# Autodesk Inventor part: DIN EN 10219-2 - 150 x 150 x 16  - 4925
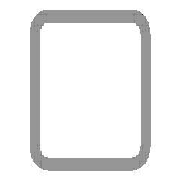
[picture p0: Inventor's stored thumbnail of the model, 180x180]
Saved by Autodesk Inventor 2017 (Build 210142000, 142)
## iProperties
IsCustomPart: 1
Created: 2017-11
Part Number: DIN EN 10219-2 - 150 x 150 x 16  - 4925
Material: Steel, Mild
Description: Cold formed welded structural hollow sections of non-alloy and fine grain structural steel
Document SubType Name: Modeling
Standard: DIN
Designer: iusti
Standard Revision: 2006-07
Standards Organization: DIN
Language: en-US
Size Designation: 150 x 150 x 16
Categories: <MemberInstance><Categories><Category DisplayName="Structural Shapes" InternalName="089c4875-fa83-4c05-b084-43b9cc11f5ed" Mnemonic="GRDR"><CategoryParameter Dis
Stock Number: 150 x 150 x 16
Density: 7.85 g/cm^3
Appearance: Semi-Polished
Mass: 289079 g
Surface Area: 46181.3 cm^2
Volume: 36825.4 cm^3
_CCFamilyMember: 76
_CCFamilyDisplayName: DIN EN 10219-2 (Square Hollow Section - Cold Formed) - Cold formed welded structural hollow sections of non-alloy and fine grain structural steel
_FrameMemberDoc: Frame Member File
_Version: 15.0.0
_GetPNFromCC: 1
G_L: 4925.000 mm
G_W: 150.000 mm
G_H: 150.000 mm
+38AB50A9-5FEF-434A-B58F-2C43C3F5CDA6+CUTDETAIL1: Cut
Author: iusti
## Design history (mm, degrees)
node "Start plane"
node "End plane"
sketch "Sketch"
  geometry: L1 (-75, -27)-(-75, 27); L2 (-27, 75)-(27, 75); L3 (75, 27)-(75, -27); L4 (27, -75)-(-27, -75); L5 (-27, 59)-(27, 59); L6 (59, 27)-(59, -27); L7 (27, -59)-(-27, -59); L8 (-59, -27)-(-59, 27); L9 (0, 153.918)-(0, -153.918) reference; L10 (-153.918, 0)-(153.918, 0) reference; A1 r 48 centre (-27, -27) between (-75, -27) and (-27, -75); A2 r 48 centre (-27, 27) between (-27, 75) and (-75, 27); A3 r 48 centre (27, 27) between (75, 27) and (27, 75); A4 r 48 centre (27, -27) between (27, -75) and (75, -27); A5 r 32 centre (-27, 27) between (-27, 59) and (-59, 27); A6 r 32 centre (27, 27) between (59, 27) and (27, 59); A7 r 32 centre (27, -27) between (27, -59) and (59, -27); A8 r 32 centre (-27, -27) between (-59, -27) and (-27, -59)
  constraints: 16 end point, 16 point on circle, 8 centre point, 8 tangent, 4 parallel, 3 equal radius, 2 perpendicular, 7 other
  dimensions: "d7" = 48 radius of A1 (= G_IR); "d10" = 150 distance between parallel lines of L2 L4 (= G_H); "d11" = 150 distance between parallel lines of L1 L3 (= G_W); "d12" = 16 distance between parallel lines of L3 L6 (= G_T); "d15" = 75 distance between parallel lines of L2 L10 (= 0.5 x d10); "d16" = 75 distance between parallel lines of L9 L3 (= 0.5 x d11)
extrude "Body" new body sketch "Sketch" stored distance "d3" = 4925 (= G_L); taper "d4" = 0 deg
node "Driven Length"
  sketch "Sketch3"
    geometry: L1 (0, 0)-(10, 0) reference
    constraints: 2 end point, 1 horizontal
  workplane "Work Plane3"
  sketch "Sketch4"
    geometry: L1 (-2, 0)-(12, 0) reference; L2 (-2, 4925)-(12, 4925) reference
    dimensions: "d18" = 4925 distance between parallel lines of L1 L2 (derived)
workplane "Work Plane4"
split "Split1"
body "Solid1"
other parameters: "G_W" = 150 [user parameter; used in 1 equation term], "G_H" = 150 [user parameter; used in 1 equation term], "G_T" = 16 [user parameter; used in 1 equation term], "G_IR" = 48 [user parameter; used in 1 equation term], "G_L" = 4925 (= d18) [user parameter; used in 1 equation term], "G_OFFSET_START" = 0 [user parameter; used in 1 equation term], "G_OFFSET_END" = -75 [user parameter; used in 1 equation term], "d13" = 0 (computed from G_OFFSET_START), "d14" = 4925 (= G_OFFSET_END + B_L), "d17" = 90 deg
